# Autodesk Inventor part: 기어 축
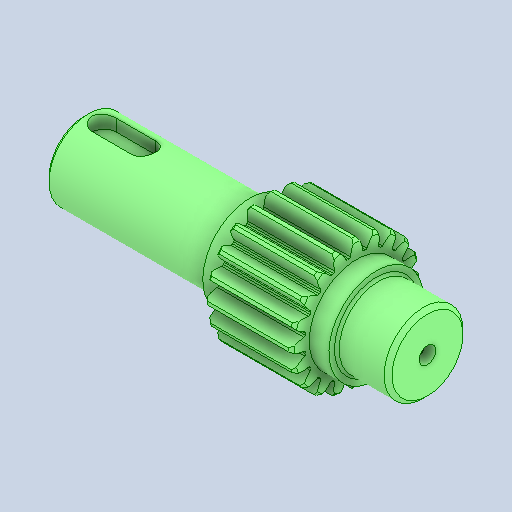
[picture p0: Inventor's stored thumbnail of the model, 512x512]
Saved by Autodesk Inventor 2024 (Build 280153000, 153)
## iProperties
Created: 2025-11
Part Number: 기어 축
Material: 강철, 합금
Document SubType Name: Modeling
Designer: Eud07
Density: 7.73 g/cm^3
Appearance: 기본값
Author: jhkim
Sending System: Autodesk Inventor 2026
Preprocessor: ST-DEVELOPER v20.1
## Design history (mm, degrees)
node "기어 축1"
node "솔리드2"
node "솔리드1"
